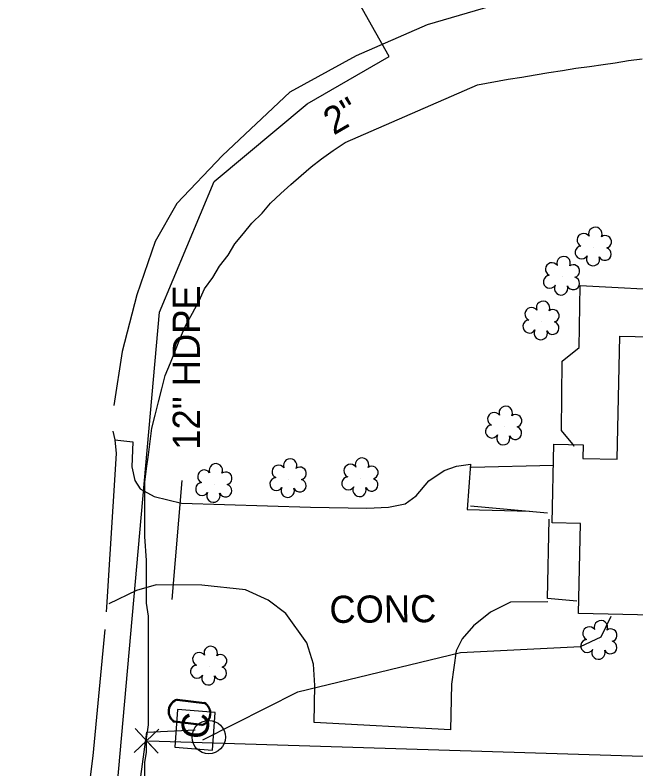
# Model space of a CAD drawing. Extents: x 3040896 to 3051146, y 687568 to 732976.
# Drawn here: x 3049457.3 to 3049548.8, y 693991.3 to 694102.3 of the extents above; entities that cross this region are included whole.
import ezdxf

# ---------------------------------------------------------------- set-up
doc = ezdxf.new("R2010")
doc.units = 0
for name, color, linetype in [('Exist Building', 7, 'Continuous'), ('Exist Other Culture Area Outline', 7, 'Continuous'), ('Exist Property Corner CELL', 7, 'Continuous'), ('Exist Property Line', 7, 'Continuous'), ('Exist Roads Change in Surface', 7, 'Continuous'), ('Exist Roads EOP', 7, 'Continuous'), ('Exist Roads EOP Other', 7, 'Continuous'), ('Exist Roads EOP Other Text', 7, 'Continuous'), ('Exist Structure Minor Pipes HDPE 12 Inch', 7, 'Continuous'), ('Exist Structure Minor Pipes HDPE 12 Inch Text', 7, 'Continuous'), ('Exist Utilities Other Pole CELL', 7, 'Continuous'), ('Exist Utilities Power UG Cable', 7, 'Continuous'), ('Exist Utilities Power UG Cable SUE', 7, 'Continuous'), ('Exist Utilities TV Pedestal CELL', 7, 'Continuous'), ('Exist Utilities TV UG Cable', 7, 'Continuous'), ('Exist Utilities Water Meter CELL', 7, 'Continuous'), ('Exist Utilities Water UG Line', 7, 'Continuous'), ('Exist Utilities Water UG Line Text', 7, 'Continuous'), ('Exist Vegetation Shrub CELL', 7, 'Continuous'), ('Old_Level_13', 7, 'Continuous')]:
    doc.layers.add(name, color=color, linetype=linetype)

msp = doc.modelspace()

# ---------------------------------------------------------------- linework, layer by layer
at = {"layer": 'Exist Building'}
msp.add_lwpolyline([(3049568.62, 694013.51), (3049540.34, 694014.13), (3049540.63, 694027.4), (3049536.46, 694027.49), (3049536.71, 694039.07), (3049541.01, 694038.98), (3049540.97, 694036.97), (3049546.03, 694036.86), (3049546.43, 694055), (3049555.48, 694054.8), (3049555.65, 694062.94), (3049568.66, 694062.66), (3049568.71, 694064.87), (3049581.32, 694064.6), (3049580.67, 694034.92), (3049569.3, 694035.17), (3049569.07, 694024.58), (3049568.86, 694024.59)], close=True, dxfattribs=at)
at = {"layer": 'Exist Other Culture Area Outline'}
for points in [[(3049539.69, 694038.76), (3049539.51, 694039.09), (3049537.81, 694041.11), (3049537.92, 694051.32), (3049540.41, 694053.31), (3049540.58, 694062.47), (3049555.45, 694061.67)], [(3049524.51, 694035.71), (3049536.64, 694036.01)], [(3049535.75, 694028.93), (3049524.4, 694029.95)], [(3049540.1, 694015.98), (3049535.75, 694016.34), (3049536.02, 694028.05)]]:
    msp.add_lwpolyline(points, dxfattribs=at)
at = {"layer": 'Exist Property Corner CELL'}
msp.add_line((3049476.7, 693995.41), (3049476.7, 693995.41), dxfattribs=at)
msp.add_lwpolyline([(3049478.52, 693997.12), (3049474.88, 693993.7), (3049476.7, 693995.41), (3049478.41, 693993.59), (3049474.99, 693997.23)], dxfattribs=at)
at = {"layer": 'Exist Property Line'}
msp.add_line((3049476.95, 693995.4), (3049784.03, 693985.96), dxfattribs=at)
at = {"layer": 'Exist Roads Change in Surface'}
msp.add_lwpolyline([(3049471.74, 694041), (3049472.03, 694039.75), (3049472.23, 694037.7), (3049470.78, 694015.1), (3049470.73, 694014.39)], dxfattribs=at)
at = {"layer": 'Exist Roads EOP'}
for points in [[(3049716.56, 694122.36), (3049712.59, 694118.9), (3049707.37, 694115.95), (3049699.59, 694112.22), (3049693.71, 694110.45), (3049686.44, 694110.04), (3049669.84, 694110.4), (3049649.98, 694111.33), (3049634.76, 694111.51), (3049609.48, 694111.82), (3049585.73, 694110.83), (3049567.15, 694109.49), (3049545.79, 694106.61), (3049527.47, 694103.61), (3049518.05, 694100.84), (3049507.59, 694096.28), (3049497.81, 694090.95), (3049487.9, 694081.62), (3049481.17, 694074.53), (3049477.94, 694068.93), (3049475.24, 694061.1), (3049473.07, 694052.72), (3049471.85, 694044.77)], [(3049470.52, 694011.81), (3049468.75, 693993.18), (3049467.11, 693979.93), (3049464.12, 693960.41), (3049461.73, 693947.94), (3049456.39, 693930.71), (3049449.18, 693909.79), (3049436.96, 693876.84), (3049427.36, 693850.37), (3049423.26, 693837.5), (3049420.85, 693829.06), (3049419.38, 693821.68)]]:
    msp.add_lwpolyline(points, dxfattribs=at)
at = {"layer": 'Exist Roads EOP Other'}
for points in [[(3049472.03, 694039.75), (3049474.67, 694039.45), (3049474.54, 694035.76), (3049474.95, 694033.72), (3049475.75, 694032.53), (3049477.81, 694031.37), (3049481.85, 694030.41), (3049500.86, 694029.81), (3049509.14, 694029.68), (3049512.35, 694029.8), (3049514.8, 694030.28), (3049516.4, 694031.48), (3049518.29, 694033.71), (3049520.51, 694035.23), (3049522.34, 694035.87), (3049524.42, 694036.12), (3049523.92, 694029.47), (3049533.08, 694029.23)], [(3049535.79, 694015.88), (3049530.29, 694015.81), (3049527.34, 694014.35), (3049524.84, 694012.33), (3049523.16, 694010.41), (3049522.29, 694008.67), (3049521.61, 694003.77), (3049521.48, 693997.01), (3049501.36, 693998.08), (3049501.49, 694003.57), (3049501.3, 694006.68), (3049500.3, 694009.83), (3049497.23, 694014.15), (3049494.6, 694016.14), (3049491.28, 694017.66), (3049484.85, 694018.34), (3049478.09, 694018.36), (3049475.19, 694017.52), (3049471.11, 694015.57)]]:
    msp.add_lwpolyline(points, dxfattribs=at)
at = {"layer": 'Exist Structure Minor Pipes HDPE 12 Inch'}
msp.add_lwpolyline([(3049480.46, 694016.19), (3049481.93, 694033.74)], dxfattribs=at)
at = {"layer": 'Exist Utilities Other Pole CELL'}
msp.add_circle((3049485.85, 693995.95), 2.46, dxfattribs=at)
at = {"layer": 'Exist Utilities Power UG Cable'}
msp.add_lwpolyline([(3049522.92, 694008.42), (3049540.63, 694009.3), (3049543.68, 694010.72), (3049545.11, 694013.77)], dxfattribs=at)
at = {"layer": 'Exist Utilities Power UG Cable SUE'}
msp.add_lwpolyline([(3049484.96, 693995.54), (3049498.95, 694002.63), (3049522.92, 694008.42)], dxfattribs=at)
at = {"layer": 'Exist Utilities TV Pedestal CELL'}
msp.add_line((3049483.83, 693997.02), (3049483.83, 693997.02), dxfattribs=at)
msp.add_lwpolyline([(3049486.38, 693994.04), (3049486.81, 693999.58), (3049481.27, 694000), (3049480.85, 693994.47), (3049486.38, 693994.04)], dxfattribs=at)
at = {"layer": 'Exist Utilities TV UG Cable'}
msp.add_lwpolyline([(3049376.2, 693638.52), (3049415.87, 693647.83), (3049417.14, 693725.83), (3049418.09, 693762.61), (3049425.7, 693818.09), (3049434.89, 693849.03), (3049438.61, 693849.55), (3049435.46, 693852.27), (3049446.66, 693882), (3049466.64, 693936.69), (3049475.7, 693989.09), (3049476.75, 693996.7), (3049483.83, 693997.02)], dxfattribs=at)
at = {"layer": 'Exist Utilities Water Meter CELL'}
msp.add_line((3049483.02, 693999.59), (3049483.02, 693999.59), dxfattribs=at)
for points in [[(3049481.18, 694001.39), (3049485.23, 694000.9)], [(3049481.2, 694001.53), (3049485.24, 694001.04)], [(3049484.83, 693997.66), (3049480.76, 693998.16)], [(3049484.85, 693997.8), (3049480.78, 693998.29)]]:
    msp.add_lwpolyline(points, dxfattribs=at)
for centre, radius, start, end in [((3049481.72, 693999.75), 1.86, 106.2668, 239.0682), ((3049481.73, 693999.74), 1.73, 108.3897, 236.8711), ((3049484.3, 693999.44), 1.86, 286.7371, 59.3971), ((3049484.31, 693999.44), 1.73, 288.2159, 57.9616)]:
    msp.add_arc(centre, radius, start, end, dxfattribs=at)
at = {"layer": 'Exist Utilities Water UG Line'}
msp.add_lwpolyline([(3049439.17, 693868.02), (3049460.93, 693929.56), (3049466.87, 693954.26), (3049472.36, 693988.56), (3049478.6, 694058.55), (3049486.63, 694077.79), (3049500.37, 694089.2), (3049512.42, 694096.18), (3049499.11, 694119.85), (3049513.38, 694125.56), (3049545.34, 694132.33), (3049574.81, 694135.99), (3049612.01, 694138.02), (3049630.92, 694139.85), (3049644.33, 694146.56), (3049651.65, 694156.52), (3049661.41, 694175.22), (3049672.79, 694182.74), (3049686.82, 694188.44), (3049699.01, 694187.83), (3049715.48, 694182.54), (3049725.36, 694173.4), (3049730.47, 694163.6), (3049731.96, 694155.59)], dxfattribs=at)
at = {"layer": 'Exist Vegetation Shrub CELL'}
for p, q in [((3049542.58, 694068.02), (3049542.58, 694068.02)), ((3049537.9, 694063.71), (3049537.9, 694063.71)), ((3049534.88, 694057.12), (3049534.88, 694057.12)), ((3049529.37, 694041.65), (3049529.37, 694041.65)), ((3049508.2, 694034.03), (3049508.2, 694034.03)), ((3049486.67, 694033.19), (3049486.67, 694033.19)), ((3049497.62, 694033.91), (3049497.62, 694033.91)), ((3049543.4, 694010.09), (3049543.4, 694010.09)), ((3049485.91, 694006.3), (3049485.91, 694006.3))]:
    msp.add_line(p, q, dxfattribs=at)
for centre, radius, start, end in [((3049542.8, 694070.06), 0.99, 334.8391, 200.4717), ((3049541.09, 694069.15), 0.968, 35.8908, 245.4216), ((3049544.25, 694068.89), 0.929, 284.4567, 126.0861), ((3049540.77, 694067.32), 0.955, 95.1099, 327.9534), ((3049544.21, 694067.09), 0.937, 204.9913, 73.4601), ((3049538.13, 694065.75), 0.99, 334.8391, 200.4717), ((3049542.45, 694066.34), 0.984, 151.2797, 21.387), ((3049536.42, 694064.84), 0.968, 35.8908, 245.4216), ((3049539.57, 694064.58), 0.929, 284.4567, 126.0861), ((3049536.1, 694063.01), 0.955, 95.1099, 327.9534), ((3049539.54, 694062.78), 0.937, 204.9913, 73.4601), ((3049537.77, 694062.03), 0.984, 151.2797, 21.387), ((3049535.1, 694059.16), 0.99, 334.8391, 200.4717), ((3049533.39, 694058.25), 0.968, 35.8908, 245.4216), ((3049536.55, 694057.99), 0.929, 284.4567, 126.0861), ((3049533.08, 694056.41), 0.955, 95.1099, 327.9534), ((3049536.51, 694056.19), 0.937, 204.9913, 73.4601), ((3049534.75, 694055.44), 0.984, 151.2797, 21.387), ((3049529.6, 694043.69), 0.99, 334.8391, 200.4717), ((3049527.89, 694042.78), 0.968, 35.8908, 245.4216), ((3049531.04, 694042.52), 0.929, 284.4567, 126.0861), ((3049527.57, 694040.95), 0.955, 95.1099, 327.9534), ((3049531.01, 694040.72), 0.937, 204.9913, 73.4601), ((3049529.24, 694039.97), 0.984, 151.2797, 21.387), ((3049486.9, 694035.23), 0.99, 334.8391, 200.4717), ((3049497.85, 694035.95), 0.99, 334.8391, 200.4717), ((3049508.43, 694036.07), 0.99, 334.8391, 200.4717), ((3049485.19, 694034.32), 0.968, 35.8908, 245.4216), ((3049496.14, 694035.04), 0.968, 35.8908, 245.4216), ((3049499.29, 694034.78), 0.929, 284.4567, 126.0861), ((3049506.72, 694035.16), 0.968, 35.8908, 245.4216), ((3049509.87, 694034.9), 0.929, 284.4567, 126.0861), ((3049488.34, 694034.06), 0.929, 284.4567, 126.0861), ((3049495.82, 694033.21), 0.955, 95.1099, 327.9534), ((3049506.4, 694033.33), 0.955, 95.1099, 327.9534), ((3049509.84, 694033.1), 0.937, 204.9913, 73.4601), ((3049484.87, 694032.49), 0.955, 95.1099, 327.9534), ((3049488.31, 694032.26), 0.937, 204.9913, 73.4601), ((3049499.26, 694032.98), 0.937, 204.9913, 73.4601), ((3049486.54, 694031.51), 0.984, 151.2797, 21.387), ((3049497.49, 694032.23), 0.984, 151.2797, 21.387), ((3049508.07, 694032.35), 0.984, 151.2797, 21.387), ((3049543.63, 694012.13), 0.99, 334.8391, 200.4717), ((3049541.92, 694011.21), 0.968, 35.8908, 245.4216), ((3049545.07, 694010.96), 0.929, 284.4567, 126.0861), ((3049541.6, 694009.38), 0.955, 95.1099, 327.9534), ((3049545.04, 694009.16), 0.937, 204.9913, 73.4601), ((3049486.14, 694008.34), 0.99, 334.8391, 200.4717), ((3049543.27, 694008.4), 0.984, 151.2797, 21.387), ((3049484.43, 694007.43), 0.968, 35.8908, 245.4216), ((3049487.58, 694007.17), 0.929, 284.4567, 126.0861), ((3049484.11, 694005.6), 0.955, 95.1099, 327.9534), ((3049487.54, 694005.37), 0.937, 204.9913, 73.4601), ((3049485.78, 694004.62), 0.984, 151.2797, 21.387)]:
    msp.add_arc(centre, radius, start, end, dxfattribs=at)
at = {"layer": 'Old_Level_13'}
for points in [[(3049476.45, 693992.19), (3049476.7, 693993.75), (3049476.7, 693995.75), (3049476.95, 693997.75), (3049476.95, 693999.75), (3049476.95, 694001.75), (3049476.95, 694003.75), (3049476.95, 694005.75), (3049476.95, 694007.75), (3049476.95, 694009.75), (3049476.95, 694011.75), (3049476.95, 694013.75), (3049476.7, 694015.69), (3049476.7, 694017.69), (3049476.7, 694019.69), (3049476.7, 694021.94), (3049476.45, 694025.5), (3049476.45, 694027.5), (3049476.45, 694029.5), (3049476.45, 694031.5), (3049476.45, 694033.5), (3049476.7, 694035.5), (3049476.95, 694037.5), (3049477.2, 694039.5), (3049477.45, 694041.44), (3049477.95, 694043.38), (3049478.45, 694045.32), (3049478.95, 694047.25), (3049479.45, 694049.19), (3049480.2, 694051.07), (3049480.95, 694052.94), (3049481.7, 694054.82), (3049482.45, 694056.63), (3049483.45, 694058.38), (3049484.45, 694060.19), (3049485.2, 694061.94), (3049486.45, 694063.63), (3049487.45, 694065.32), (3049488.7, 694066.94), (3049489.7, 694068.57), (3049490.95, 694070.13), (3049492.2, 694071.63), (3049493.7, 694073.13), (3049494.95, 694074.57), (3049496.45, 694076), (3049497.95, 694077.32), (3049499.45, 694078.63), (3049500.95, 694079.94), (3049502.45, 694081.13), (3049504.2, 694082.32), (3049505.95, 694083.5), (3049525.45, 694092), (3049529.95, 694092.82), (3049531.95, 694093.13), (3049533.95, 694093.5), (3049535.95, 694093.82), (3049537.95, 694094.13), (3049539.95, 694094.44), (3049541.95, 694094.69), (3049543.95, 694095), (3049545.7, 694095.25), (3049547.7, 694095.57), (3049549.7, 694095.82)], [(3049476.45, 693992.19), (3049476.7, 693993.75), (3049476.7, 693995.75), (3049476.95, 693997.75), (3049476.95, 693999.75), (3049476.95, 694001.75), (3049476.95, 694003.75), (3049476.95, 694005.75), (3049476.95, 694007.75), (3049476.95, 694009.75), (3049476.95, 694011.75), (3049476.95, 694013.75), (3049476.7, 694015.69), (3049476.7, 694017.69), (3049476.7, 694019.69), (3049476.7, 694021.94), (3049476.45, 694025.5), (3049476.45, 694027.5), (3049476.45, 694029.5), (3049476.45, 694031.5), (3049476.45, 694033.5), (3049476.7, 694035.5), (3049476.95, 694037.5), (3049477.2, 694039.5), (3049477.45, 694041.44), (3049477.95, 694043.38), (3049478.45, 694045.32), (3049478.95, 694047.25), (3049479.45, 694049.19), (3049480.2, 694051.07), (3049480.95, 694052.94), (3049481.7, 694054.82), (3049482.45, 694056.63), (3049483.45, 694058.38), (3049484.45, 694060.19), (3049485.2, 694061.94), (3049486.45, 694063.63), (3049487.45, 694065.32), (3049488.7, 694066.94), (3049489.7, 694068.57), (3049490.95, 694070.13), (3049492.2, 694071.63), (3049493.7, 694073.13), (3049494.95, 694074.57), (3049496.45, 694076), (3049497.95, 694077.32), (3049499.45, 694078.63), (3049500.95, 694079.94), (3049502.45, 694081.13), (3049504.2, 694082.32), (3049505.95, 694083.5), (3049525.45, 694092), (3049529.95, 694092.82), (3049531.95, 694093.13), (3049533.95, 694093.5), (3049535.95, 694093.82), (3049537.95, 694094.13), (3049539.95, 694094.44), (3049541.95, 694094.69), (3049543.95, 694095), (3049545.7, 694095.25), (3049547.7, 694095.57), (3049549.7, 694095.82)], [(3049476.45, 693989.75), (3049476.45, 693992.19)], [(3049476.45, 693989.75), (3049476.45, 693992.19)]]:
    msp.add_lwpolyline(points, dxfattribs=at)

# ---------------------------------------------------------------- texts
at = {"layer": 'Exist Roads EOP Other Text'}
msp.add_text('CONC', height=4, rotation=0.4254, dxfattribs=at).set_placement((3049503.64, 694012.76))
at = {"layer": 'Exist Structure Minor Pipes HDPE 12 Inch Text'}
msp.add_text('12" HDPE', height=4, rotation=90, dxfattribs=at).set_placement((3049484.54, 694038.28))
at = {"layer": 'Exist Utilities TV Pedestal CELL'}
msp.add_text('C', height=4, rotation=85.6153, dxfattribs=at).set_placement((3049485.72, 693995.56))
at = {"layer": 'Exist Utilities Water UG Line Text'}
msp.add_text('2"', height=4, rotation=30.0686, dxfattribs=at).set_placement((3049504.25, 694084.52))

doc.saveas('drawing.dxf')
